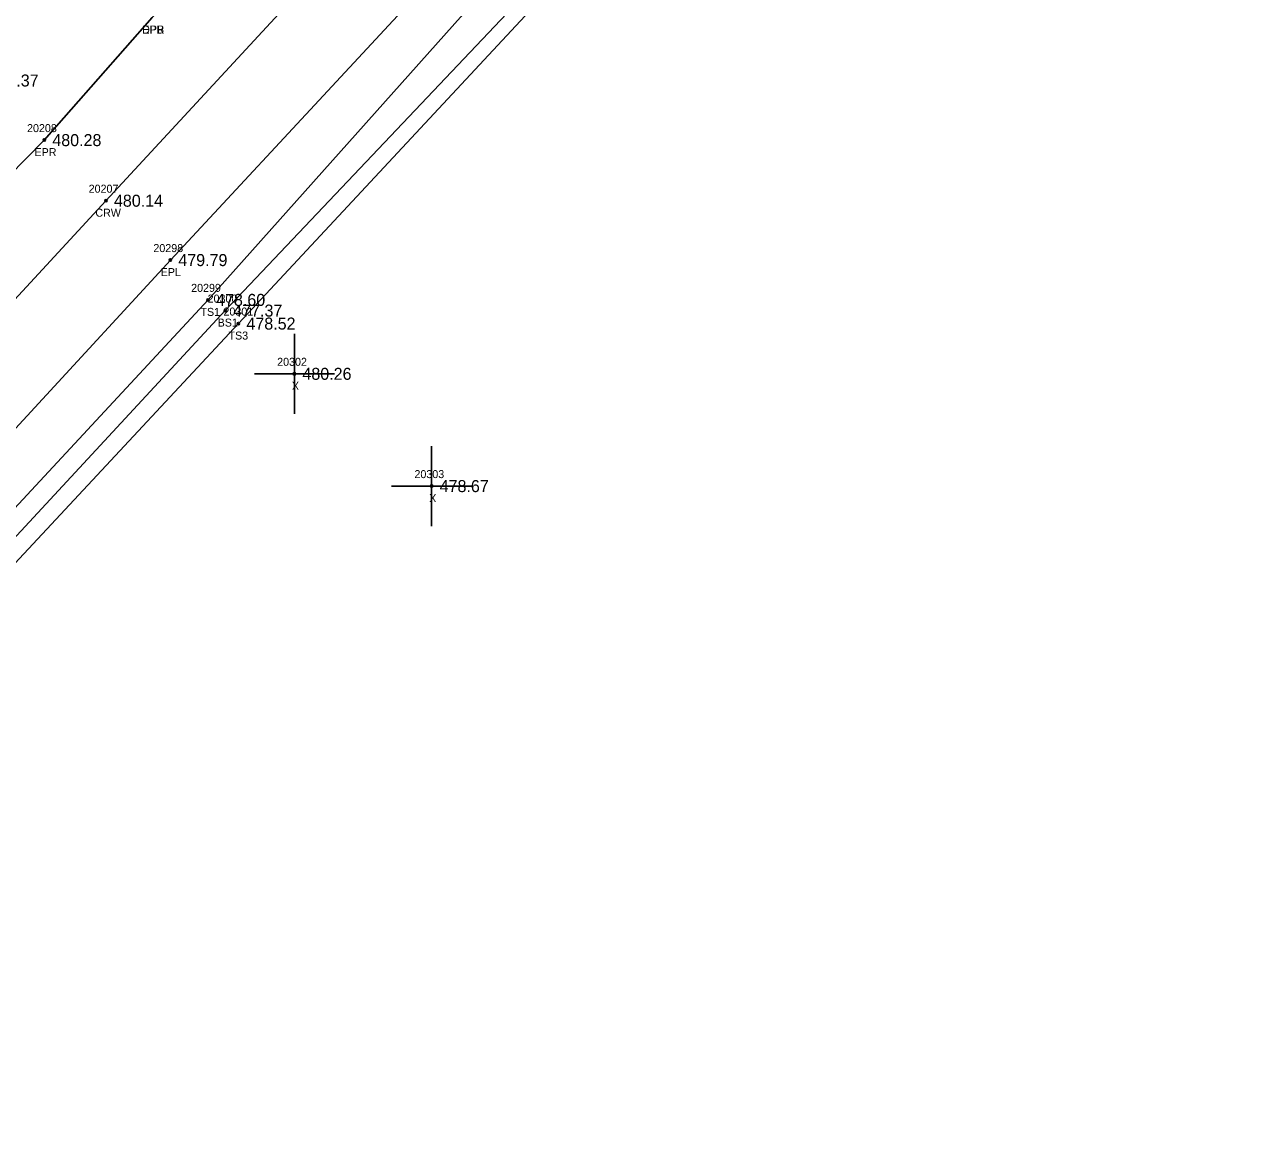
# Model space of a CAD drawing. Extents: x 1741010 to 1742139, y 749382 to 750625.
# Drawn here: x 1741801.4 to 1741955, y 750183.8 to 750322.1 of the extents above; entities that cross this region are included whole.
import ezdxf

# ---------------------------------------------------------------- set-up
doc = ezdxf.new("R2010")
doc.units = 0
for name, color, linetype in [('RD_DTM_BkLn1', 7, 'Continuous'), ('RD_DTM_BkLn2', 7, 'Continuous'), ('RD_DTM_BkLn_txCode', 7, 'Continuous'), ('RD_EX_Driveway_txCode', 7, 'Continuous'), ('RD_EX_Misc', 7, 'Continuous'), ('RD_EX_Misc_txCode', 7, 'Continuous'), ('RD_EX_Road', 7, 'Continuous'), ('RD_EX_Road_txCode', 7, 'Continuous'), ('RD_EX_TX_Misc_ELEV', 7, 'Continuous'), ('RD_EX_TX_Road_ELEV', 7, 'Continuous'), ('RD_HC_Survey_ELEV', 7, 'Continuous'), ('RD_HC_Survey_txCode', 7, 'Continuous'), ('RD_SMD_Locator', 7, 'Continuous')]:
    doc.layers.add(name, color=color, linetype=linetype)

msp = doc.modelspace()

# ---------------------------------------------------------------- linework, layer by layer
at = {"layer": 'RD_DTM_BkLn1'}
msp.add_lwpolyline([(1742095.1, 750579.47), (1742056.96, 750547.11), (1742019.74, 750514.22), (1741983.45, 750480.17), (1741948.01, 750445.01), (1741913.15, 750409.3), (1741879.03, 750372.99), (1741811.59, 750300.09), (1741743.65, 750226.52), (1741676.29, 750153.06), (1741642.32, 750115.53), (1741610.32, 750077.63)], dxfattribs=at)
at = {"layer": 'RD_DTM_BkLn2'}
for points in [[(1742105.6, 750567.48), (1742094.25, 750560.49), (1742091.64, 750555.7), (1742067.93, 750534.94), (1742031.73, 750501.95), (1741994.85, 750467.63), (1741959.82, 750432.06), (1741925.8, 750396.31), (1741891.25, 750362.62), (1741824.36, 750287.7), (1741756.44, 750214.6), (1741688.69, 750142.04), (1741655.55, 750103.43), (1741644.64, 750083.31), (1741626.06, 750060.3), (1741620, 750055.3), (1741614.97, 750059.12), (1741617.5, 750064.27), (1741619.23, 750067.96)], [(1742107.37, 750564.98), (1742099.21, 750558.66), (1742095.99, 750559.5), (1742095.15, 750554.39), (1742069.73, 750532.61), (1742034.06, 750499.81), (1741997.6, 750464.99), (1741961.88, 750429.54), (1741928.13, 750394.17), (1741895.34, 750359.02), (1741826.5, 750286.36), (1741758.73, 750213.29), (1741690.1, 750140.59), (1741658.36, 750099.77), (1741650.43, 750077.87), (1741632.9, 750061.59), (1741621.97, 750051.56), (1741618.99, 750048.78), (1741611.88, 750047.79)], [(1742108.6, 750563.87), (1742101.48, 750556.48), (1742102.57, 750548.5), (1742101.05, 750532.99), (1742105.06, 750513.92), (1742103.27, 750510.53), (1742100.54, 750509.6), (1742099.13, 750514.58), (1742095.78, 750530.6), (1742094.19, 750550.08), (1742071, 750531.59), (1742035.26, 750498.87), (1741998.91, 750463.73), (1741964.71, 750427.12), (1741930.26, 750392.09), (1741896.36, 750357.96), (1741828.15, 750284.74), (1741760.22, 750211.9), (1741691.37, 750138.81), (1741661.95, 750096.11), (1741655.14, 750072.69), (1741637.21, 750056.01), (1741627.61, 750046.43), (1741623.09, 750045.5)]]:
    msp.add_lwpolyline(points, dxfattribs=at)
at = {"layer": 'RD_EX_Misc'}
for p, q in [((1741835.15, 750273.46), (1741835.15, 750283.46)), ((1741830.15, 750278.46), (1741840.15, 750278.46)), ((1741852.3, 750259.43), (1741852.3, 750269.43)), ((1741847.3, 750264.43), (1741857.3, 750264.43))]:
    msp.add_line(p, q, dxfattribs=at)
at = {"layer": 'RD_EX_Road'}
for points in [[(1742095.24, 750593.27), (1742088.27, 750587.97), (1742078.23, 750580.89), (1742049.13, 750555.21), (1742012.94, 750522.73), (1741975.54, 750488.03), (1741940.71, 750452.82), (1741916.22, 750428.67), (1741904.72, 750416.99), (1741884.38, 750395.02), (1741870.75, 750380.27), (1741817.36, 750322.98), (1741803.89, 750307.66), (1741783.86, 750287.33), (1741735.44, 750234.07), (1741718.84, 750214.98), (1741710.25, 750205.58), (1741668.97, 750159.8), (1741635, 750122.49), (1741604.35, 750087.7), (1741600.63, 750085.47)], [(1742102.43, 750570.61), (1742093.26, 750562.71), (1742064.72, 750538.42), (1742027.92, 750505.65), (1741991.25, 750471.83), (1741956.32, 750436.98), (1741921.43, 750401.39), (1741886.79, 750364.93), (1741819.64, 750292.67), (1741751.78, 750219.01), (1741684.42, 750145.59), (1741650.98, 750108.5), (1741637.17, 750092.42), (1741621.17, 750073.94), (1741621.31, 750072.22), (1741619.24, 750070.27)]]:
    msp.add_lwpolyline(points, dxfattribs=at)
at = {"layer": 'RD_SMD_Locator'}
for centre in [(1741803.89, 750307.66), (1741811.59, 750300.09), (1741819.64, 750292.67), (1741824.36, 750287.7), (1741826.5, 750286.36), (1741828.15, 750284.74), (1741835.15, 750278.46), (1741852.3, 750264.43)]:
    msp.add_circle(centre, 0.15, dxfattribs=at)

# ---------------------------------------------------------------- texts
at = {"layer": 'RD_DTM_BkLn_txCode'}
for s, p in [('20299', (1741822.24, 750288.7)), ('20300', (1741824.3, 750287.36)), ('TS1', (1741823.4, 750285.7)), ('20301', (1741826.28, 750285.74)), ('BS1', (1741825.55, 750284.36)), ('TS3', (1741826.91, 750282.74))]:
    msp.add_text(s, height=1, dxfattribs=at).set_placement(p)
at = {"layer": 'RD_EX_Driveway_txCode'}
msp.add_text('DPB', height=1, dxfattribs=at).set_placement((1741816.11, 750320.98))
at = {"layer": 'RD_EX_Misc_txCode'}
for s, p in [('20302', (1741832.99, 750279.46)), ('X', (1741834.83, 750276.46)), ('20303', (1741850.15, 750265.43)), ('X', (1741851.99, 750262.43))]:
    msp.add_text(s, height=1, dxfattribs=at).set_placement(p)
at = {"layer": 'RD_EX_Road_txCode'}
for s, p in [('EPR', (1741816.13, 750320.98)), ('20208', (1741801.73, 750308.66)), ('EPR', (1741802.66, 750305.66)), ('20298', (1741817.52, 750293.67)), ('EPL', (1741818.43, 750290.67))]:
    msp.add_text(s, height=1, dxfattribs=at).set_placement(p)
at = {"layer": 'RD_EX_TX_Misc_ELEV'}
for s, p in [('480.37', (1741797.04, 750314.36)), ('478.60', (1741825.36, 750286.95)), ('477.37', (1741827.5, 750285.61)), ('478.52', (1741829.15, 750283.99)), ('480.26', (1741836.15, 750277.71)), ('478.67', (1741853.3, 750263.68))]:
    msp.add_text(s, height=1.5, dxfattribs=at).set_placement(p)
at = {"layer": 'RD_EX_TX_Road_ELEV'}
for s, p in [('480.28', (1741804.89, 750306.91)), ('479.79', (1741820.64, 750291.92))]:
    msp.add_text(s, height=1.5, dxfattribs=at).set_placement(p)
at = {"layer": 'RD_HC_Survey_ELEV'}
msp.add_text('480.14', height=1.5, dxfattribs=at).set_placement((1741812.59, 750299.34))
at = {"layer": 'RD_HC_Survey_txCode'}
for s, p in [('20207', (1741809.43, 750301.09)), ('CRW', (1741810.27, 750298.09))]:
    msp.add_text(s, height=1, dxfattribs=at).set_placement(p)

doc.saveas('drawing.dxf')
